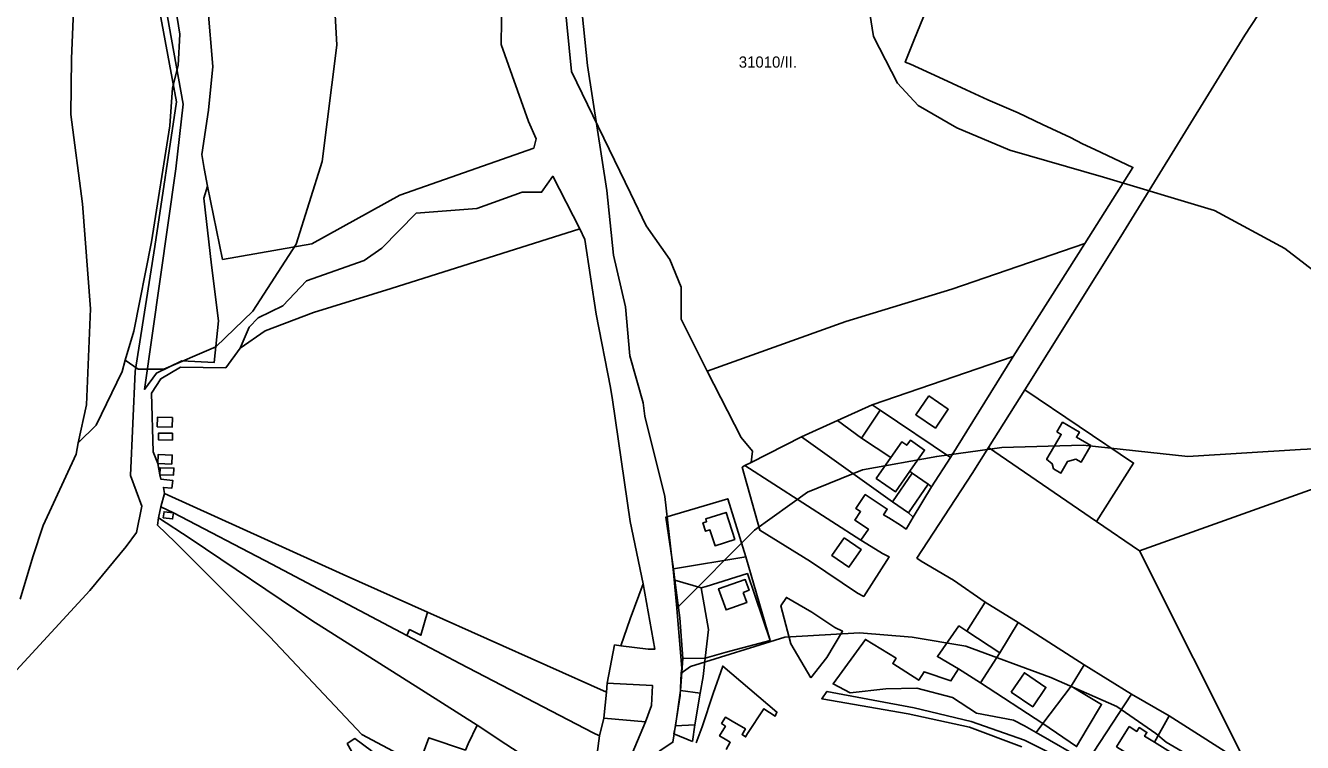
# Model space of a CAD drawing. Extents: x -532083 to -529270, y -1180561 to -1176456.
# Drawn here: x -530779 to -530208, y -1178000 to -1177679 of the extents above; entities that cross this region are included whole.
import ezdxf

# ---------------------------------------------------------------- set-up
doc = ezdxf.new("R2010")
doc.units = 0
for name, color, linetype in [('95560013', 7, 'Continuous'), ('95590013', 7, 'Continuous'), ('95660013', 7, 'Continuous')]:
    doc.layers.add(name, color=color, linetype=linetype)

msp = doc.modelspace()

# ---------------------------------------------------------------- linework, layer by layer
at = {"layer": '95560013'}
for points in [[(-530202.5013, -1177886.43345), (-530280.6013, -1177914.22245), (-530299.8523, -1177901.09045), (-530283.3193, -1177875.02245), (-530332.0333, -1177842.15945), (-530288.9793, -1177773.56145), (-530233.5283, -1177683.50645), (-530208.8843, -1177645.54245), (-530157.0203, -1177563.79845)], [(-530697.4183, -1177670.94245), (-530695.2093, -1177697.53345), (-530697.1583, -1177717.08545), (-530700.1473, -1177736.89845), (-530699.0133, -1177743.09345), (-530697.5383, -1177751.04345), (-530699.1973, -1177756.40545), (-530695.6953, -1177786.35945), (-530692.5613, -1177811.32045), (-530694.5893, -1177829.99545), (-530708.9673, -1177829.25545), (-530720.3953, -1177834.80245), (-530725.7413, -1177842.01345), (-530711.7323, -1177743.27845), (-530708.3573, -1177714.30045), (-530714.6403, -1177679.39445), (-530730.3473, -1177590.91845)], [(-530724.2453, -1177644.04445), (-530711.3873, -1177713.36945), (-530721.0713, -1177777.99645), (-530729.9633, -1177834.02345), (-530731.9083, -1177880.57345), (-530726.9063, -1177894.23145), (-530729.2793, -1177906.09545), (-530733.9793, -1177912.38145), (-530750.1173, -1177932.02645), (-530783.0193, -1177967.70045)], [(-530565.7593, -1177655.31045), (-530566.2513, -1177687.61045), (-530553.9603, -1177722.12945), (-530550.5203, -1177729.84245), (-530551.6063, -1177733.98045), (-530611.5383, -1177755.10845), (-530650.8423, -1177776.89045), (-530690.7973, -1177783.86045), (-530697.5383, -1177751.04345), (-530699.0133, -1177743.09345), (-530700.1473, -1177736.89845), (-530697.1583, -1177717.08545), (-530695.2093, -1177697.53345), (-530697.4183, -1177670.94245)], [(-530377.2153, -1177675.24945), (-530381.6163, -1177685.84645), (-530385.4313, -1177695.55945), (-530383.0843, -1177696.44245), (-530370.4663, -1177702.32945), (-530358.1413, -1177707.92145), (-530348.4583, -1177712.33645), (-530334.9603, -1177718.22345), (-530324.1023, -1177723.52145), (-530311.5343, -1177729.32645), (-530306.2033, -1177732.05745), (-530300.6273, -1177734.70645), (-530283.6203, -1177742.69945), (-530305.1713, -1177776.72145), (-530364.5583, -1177797.10745), (-530412.0683, -1177811.66845), (-530474.0943, -1177833.90845), (-530485.7083, -1177810.60945), (-530485.7083, -1177796.31245), (-530490.7233, -1177783.86945), (-530501.2803, -1177768.77845), (-530508.3383, -1177754.18245), (-530534.7493, -1177699.73945), (-530538.8693, -1177657.20545)], [(-530232.5793, -1178010.35345), (-530280.6013, -1177914.22245), (-530202.5013, -1177886.43345)], [(-530333.2913, -1178002.05245), (-530356.6913, -1177993.25045), (-530384.1853, -1177987.18745), (-530422.7943, -1177980.53745), (-530420.4543, -1177977.21245), (-530381.4553, -1177984.64445), (-530355.9113, -1177990.70845), (-530332.1213, -1177999.11845), (-530297.6073, -1178016.33145)]]:
    msp.add_lwpolyline(points, dxfattribs=at)
for points in [[(-530615.4473, -1177796.92945), (-530650.1913, -1177807.60245), (-530671.6883, -1177815.87945), (-530682.9803, -1177823.50345), (-530678.8543, -1177814.13745), (-530674.9463, -1177809.99845), (-530663.8713, -1177804.55345), (-530653.2313, -1177793.44445), (-530627.3903, -1177784.29645), (-530619.5733, -1177778.85045), (-530604.1553, -1177763.16845), (-530577.0123, -1177760.98945), (-530556.8173, -1177753.80145), (-530548.1313, -1177753.80145), (-530543.1373, -1177746.61345), (-530530.9773, -1177770.13845)], [(-530502.6283, -1177929.02645), (-530508.5273, -1177944.77045), (-530512.6073, -1177956.83045), (-530515.4893, -1177956.38545), (-530518.8153, -1177973.51245), (-530519.0373, -1177977.51645), (-530599.0883, -1177941.70445), (-530636.7923, -1177924.96145), (-530716.7173, -1177888.65345), (-530717.2883, -1177885.88245), (-530713.4193, -1177886.19645), (-530713.0013, -1177882.84045), (-530718.4383, -1177882.21145), (-530718.8563, -1177880.21845), (-530712.6943, -1177880.42345), (-530712.5903, -1177877.27745), (-530718.7523, -1177877.07245), (-530718.8563, -1177880.21845), (-530719.7973, -1177875.18445), (-530713.5243, -1177875.49945), (-530713.3193, -1177871.41345), (-530719.5933, -1177871.09945), (-530719.7973, -1177875.18445), (-530721.8623, -1177870.03945), (-530722.5973, -1177843.68445), (-530718.3713, -1177837.23345), (-530709.5523, -1177832.07345), (-530689.3413, -1177832.44145), (-530682.9803, -1177823.50345), (-530671.6883, -1177815.87945), (-530650.1913, -1177807.60245), (-530615.4473, -1177796.92945), (-530530.9773, -1177770.13845), (-530528.8123, -1177774.98245), (-530523.7273, -1177808.29445), (-530517.2123, -1177841.12945), (-530516.4183, -1177846.70745), (-530508.4383, -1177901.09845)], [(-530400.1913, -1177848.99945), (-530415.7633, -1177855.88245), (-530431.8643, -1177863.29545), (-530454.2993, -1177874.68045), (-530453.7713, -1177869.65045), (-530458.7863, -1177863.56045), (-530474.0943, -1177833.90845), (-530412.0683, -1177811.66845), (-530364.5583, -1177797.10745), (-530305.1713, -1177776.72145), (-530337.1083, -1177827.28945)], [(-530365.1643, -1177872.50345), (-530396.6533, -1177851.28145), (-530400.1913, -1177848.99945), (-530337.1083, -1177827.28945)], [(-530374.9723, -1177844.91245), (-530380.7603, -1177853.37545), (-530371.9853, -1177859.37745), (-530366.1973, -1177850.91445)], [(-530299.8523, -1177901.09045), (-530348.2853, -1177868.05345), (-530332.0333, -1177842.15945), (-530283.3193, -1177875.02245)], [(-530391.9283, -1177872.58045), (-530405.0173, -1177863.86645), (-530396.6533, -1177851.28145), (-530365.1643, -1177872.50345), (-530373.7743, -1177885.58245), (-530375.1473, -1177884.52245), (-530382.3563, -1177879.58145), (-530383.3533, -1177878.58145), (-530376.8033, -1177869.22245), (-530383.1533, -1177864.77845), (-530384.7493, -1177867.05845), (-530386.9743, -1177865.50045)], [(-530720.0073, -1177858.82345), (-530713.3153, -1177858.92845), (-530713.2473, -1177854.63445), (-530719.9393, -1177854.52945)], [(-530317.6183, -1177861.06045), (-530315.7093, -1177862.17445), (-530322.0823, -1177873.09245), (-530322.2123, -1177873.31545), (-530319.6763, -1177875.30045), (-530319.1733, -1177877.52545), (-530315.8523, -1177879.46445), (-530312.8153, -1177874.26245), (-530309.1083, -1177873.29845), (-530306.7753, -1177874.66045), (-530302.4283, -1177867.21445), (-530308.8963, -1177863.43845), (-530307.5593, -1177861.14845), (-530315.1003, -1177856.74745)], [(-530713.1593, -1177861.66145), (-530719.4333, -1177861.55645), (-530719.4843, -1177864.59145), (-530713.2103, -1177864.69645)], [(-530299.8523, -1177901.09045), (-530280.6013, -1177914.22245), (-530232.5793, -1178010.35345), (-530267.4413, -1177988.16645), (-530284.2703, -1177978.51945), (-530305.4283, -1177965.25545), (-530335.0003, -1177946.44445), (-530349.6663, -1177937.28045), (-530363.9053, -1177927.50045), (-530378.2703, -1177918.86645), (-530380.2003, -1177917.50445), (-530355.5573, -1177879.63945), (-530348.2853, -1177868.05345)], [(-530608.4353, -1177952.19945), (-530668.8223, -1177920.26645), (-530712.7923, -1177897.31445), (-530718.4333, -1177894.56345), (-530716.7173, -1177888.65345), (-530636.7923, -1177924.96145), (-530599.0883, -1177941.70445), (-530602.0833, -1177952.09945), (-530607.1643, -1177949.55145)], [(-530456.7093, -1177916.98245), (-530489.1413, -1177922.40445), (-530492.6063, -1177899.23245), (-530464.8373, -1177890.96345)], [(-530712.7923, -1177897.31445), (-530716.9743, -1177896.78945), (-530717.3163, -1177899.51345), (-530713.1333, -1177900.03745), (-530712.7923, -1177897.31445), (-530668.8223, -1177920.26645), (-530608.4353, -1177952.19945), (-530584.7443, -1177964.72645), (-530525.0113, -1177995.73245), (-530522.1413, -1177997.17145), (-530523.1853, -1178005.02045), (-530525.5593, -1178018.51045), (-530526.7383, -1178025.09845), (-530532.6323, -1178021.21245), (-530564.1223, -1178000.77445), (-530576.9413, -1177992.26245), (-530600.2423, -1177977.59245), (-530650.8093, -1177945.51745), (-530705.3423, -1177908.71845), (-530719.4713, -1177899.51845), (-530718.4333, -1177894.56345)], [(-530474.3213, -1177901.24245), (-530475.9523, -1177901.76545), (-530474.7453, -1177905.52645), (-530472.8183, -1177904.90845), (-530470.5333, -1177912.03145), (-530461.6993, -1177909.19745), (-530465.5793, -1177897.10145), (-530474.7103, -1177900.03145)], [(-530456.0163, -1177924.49045), (-530474.4503, -1177930.32945), (-530476.6673, -1177930.88545), (-530488.4483, -1177927.40945), (-530489.1413, -1177922.40445), (-530456.7093, -1177916.98245), (-530445.8983, -1177954.38045)], [(-530445.8983, -1177954.38045), (-530465.5673, -1177959.61645), (-530474.9823, -1177962.40345), (-530473.4803, -1177949.51545), (-530476.6673, -1177930.88545), (-530474.4503, -1177930.32945), (-530456.0163, -1177924.49045)], [(-530500.4103, -1177958.38745), (-530512.6063, -1177956.83045), (-530508.5273, -1177944.77045), (-530502.6283, -1177929.02645), (-530497.5273, -1177958.38745)], [(-530484.8593, -1177962.55745), (-530486.2483, -1177944.29045), (-530488.4483, -1177927.40945), (-530476.6673, -1177930.88545), (-530473.4803, -1177949.51545), (-530474.9823, -1177962.40345)], [(-530457.9603, -1177932.88445), (-530455.2993, -1177931.95345), (-530456.9863, -1177927.13145), (-530468.9063, -1177931.30245), (-530465.6143, -1177940.71045), (-530456.3553, -1177937.47045)], [(-530525.0113, -1177995.73245), (-530584.7443, -1177964.72645), (-530608.4353, -1177952.19945), (-530607.1643, -1177949.55145), (-530602.0833, -1177952.09945), (-530599.0883, -1177941.70445), (-530519.0373, -1177977.51645), (-530520.3153, -1177989.19045), (-530522.1413, -1177997.17145)], [(-530353.5713, -1177986.99145), (-530364.2963, -1177979.95045), (-530380.2853, -1177975.84345), (-530394.1303, -1177976.03845), (-530410.1203, -1177977.79845), (-530417.7243, -1177973.88745), (-530403.2813, -1177953.92045), (-530389.5683, -1177962.41245), (-530391.0643, -1177964.75145), (-530379.4053, -1177972.21145), (-530376.9893, -1177968.43645), (-530365.0533, -1177972.49045), (-530361.6873, -1177967.18445), (-530351.8303, -1177973.45545), (-530323.9403, -1177991.54245), (-530326.8563, -1177995.59845), (-530332.1213, -1177992.66445), (-530336.9963, -1177990.12145)], [(-530486.0203, -1177976.84045), (-530484.8593, -1177962.55745), (-530474.9823, -1177962.40345), (-530475.7773, -1177970.58645), (-530477.1133, -1177977.95745)], [(-530501.6653, -1177990.89145), (-530520.3153, -1177989.19045), (-530519.0373, -1177977.51645), (-530518.8153, -1177973.51245), (-530498.4773, -1177974.59045), (-530498.9263, -1177983.56545)], [(-530479.5623, -1177992.25245), (-530488.2473, -1177992.69945), (-530486.0203, -1177976.84045), (-530477.1133, -1177977.95745)], [(-530507.5343, -1178005.02045), (-530523.1853, -1178005.02045), (-530522.1413, -1177997.17145), (-530520.3153, -1177989.19045), (-530501.6653, -1177990.89145)], [(-530480.6763, -1177999.62345), (-530488.9153, -1177996.27345), (-530488.2473, -1177992.69945), (-530479.5623, -1177992.25245)]]:
    msp.add_lwpolyline(points, close=True, dxfattribs=at)
at = {"layer": '95590013'}
for points in [[(-530405.0173, -1177863.86645), (-530415.7633, -1177855.88245), (-530400.1913, -1177848.99945), (-530396.6533, -1177851.28145)], [(-530391.1313, -1177892.38445), (-530431.8643, -1177863.29545), (-530415.7633, -1177855.88245), (-530405.0173, -1177863.86645), (-530391.9283, -1177872.58045), (-530398.4473, -1177881.89545), (-530389.8723, -1177887.89645), (-530383.3533, -1177878.58145), (-530382.3563, -1177879.58145)], [(-530392.7263, -1177899.58645), (-530395.1533, -1177898.14145), (-530393.4843, -1177895.59645), (-530403.3703, -1177889.11245), (-530407.4843, -1177895.38545), (-530405.4473, -1177896.72145), (-530407.9883, -1177900.59445), (-530401.9003, -1177904.58745), (-530405.2943, -1177909.48145), (-530457.1723, -1177876.16545), (-530454.2993, -1177874.68045), (-530431.8643, -1177863.29545), (-530391.1313, -1177892.38445), (-530383.9223, -1177897.32545), (-530381.8923, -1177899.15445), (-530385.0903, -1177904.58345), (-530387.6443, -1177902.75245)], [(-530427.8963, -1177919.14245), (-530450.5283, -1177905.07245), (-530458.3293, -1177876.89045), (-530457.1723, -1177876.16545), (-530405.2943, -1177909.48145), (-530400.7033, -1177912.38945), (-530395.6213, -1177915.55545), (-530392.7173, -1177916.92145), (-530404.0333, -1177934.68845), (-530406.7393, -1177933.20845)], [(-530381.8923, -1177899.15445), (-530383.9223, -1177897.32545), (-530375.1473, -1177884.52245), (-530373.7743, -1177885.58245)], [(-530602.9683, -1178010.16445), (-530628.5003, -1177996.48945), (-530669.6483, -1177952.72845), (-530712.0353, -1177910.45945), (-530719.9673, -1177902.75145), (-530719.4713, -1177899.51845), (-530705.3423, -1177908.71845), (-530650.8093, -1177945.51745), (-530600.2423, -1177977.59245), (-530576.9413, -1177992.26245), (-530580.9073, -1178000.71645), (-530582.1473, -1178003.45145), (-530598.5073, -1177997.98145)], [(-530412.7913, -1177908.43145), (-530418.2533, -1177916.39045), (-530410.6753, -1177921.59145), (-530405.2133, -1177913.63245)], [(-530427.6603, -1177971.09045), (-530436.5843, -1177955.98445), (-530441.0473, -1177938.92045), (-530438.6323, -1177935.14745), (-530427.1953, -1177941.77645), (-530416.9603, -1177948.58145), (-530413.5103, -1177950.29845), (-530420.5063, -1177962.10045)], [(-530343.1743, -1177959.94945), (-530357.8403, -1177950.30345), (-530349.6663, -1177937.28045), (-530335.0003, -1177946.44445)], [(-530361.6873, -1177967.18445), (-530371.0643, -1177961.63745), (-530361.4473, -1177947.89145), (-530357.8403, -1177950.30345), (-530343.1743, -1177959.94945), (-530351.8303, -1177973.45545)], [(-530323.9403, -1177991.54245), (-530351.8303, -1177973.45545), (-530343.1743, -1177959.94945), (-530335.0003, -1177946.44445), (-530305.4283, -1177965.25545), (-530311.1983, -1177974.90245)], [(-530304.0423, -1178008.70245), (-530326.8563, -1177995.59845), (-530323.9403, -1177991.54245), (-530308.7943, -1178001.91245), (-530304.0193, -1177993.75745), (-530297.6613, -1177983.05845), (-530307.3683, -1177977.28945), (-530311.1983, -1177974.90245), (-530305.4283, -1177965.25545), (-530284.2703, -1177978.51945)], [(-530338.0683, -1177977.50345), (-530328.4283, -1177984.08745), (-530322.5423, -1177975.46945), (-530332.1823, -1177968.88545)], [(-530285.3103, -1177992.98445), (-530290.8923, -1178001.98745), (-530279.6113, -1178008.98245), (-530286.1023, -1178019.26545), (-530304.0423, -1178008.70245), (-530284.2703, -1177978.51945), (-530267.4413, -1177988.16645), (-530274.0223, -1177999.96945), (-530278.3863, -1177997.26345), (-530277.3233, -1177995.55045), (-530280.8163, -1177993.38445), (-530281.8853, -1177995.10845)], [(-530263.1133, -1178020.00045), (-530281.8123, -1178022.00345), (-530286.1023, -1178019.26545), (-530279.6113, -1178008.98245), (-530268.7783, -1178015.70045), (-530263.1893, -1178006.68745), (-530274.0223, -1177999.96945), (-530267.4413, -1177988.16645), (-530232.5793, -1178010.35345)], [(-530597.8053, -1178066.93145), (-530612.5853, -1178040.44245), (-530635.0663, -1178000.54745), (-530631.7043, -1177998.35545), (-530624.2133, -1178003.87245), (-530592.2873, -1178064.95445), (-530595.8353, -1178066.53645)]]:
    msp.add_lwpolyline(points, close=True, dxfattribs=at)
msp.add_lwpolyline([(-530478.8943, -1178000.29345), (-530476.2223, -1177993.14645), (-530471.3233, -1177978.18045), (-530467.0923, -1177965.89545), (-530442.8203, -1177986.44545), (-530443.6013, -1177988.29045), (-530448.6713, -1177984.95945), (-530455.9423, -1177996.02445), (-530456.8593, -1177997.61645), (-530458.3993, -1177996.58545), (-530456.9193, -1177994.00945), (-530462.8693, -1177990.59245), (-530465.9033, -1177988.78945), (-530467.5933, -1177991.56445), (-530465.9033, -1177992.79745), (-530468.5163, -1177997.11345), (-530465.2903, -1177999.08345), (-530463.7443, -1177999.97145), (-530465.5903, -1178003.18545)], dxfattribs=at)
at = {"layer": '95660013'}
for points in [[(-530781.3753, -1177936.00045), (-530775.6253, -1177917.00045), (-530771.0003, -1177903.00045), (-530756.3123, -1177871.00045), (-530755.3123, -1177866.00045), (-530747.3753, -1177858.00045), (-530735.6873, -1177834.00045), (-530734.3753, -1177829.00045), (-530728.5003, -1177833.00045), (-530717.1253, -1177833.00045), (-530693.8123, -1177823.00045), (-530677.1873, -1177807.00045), (-530657.8753, -1177777.00045), (-530646.3123, -1177740.00045), (-530639.6253, -1177688.00045), (-530641.8753, -1177647.00045)], [(-530641.8753, -1177647.00045), (-530639.6253, -1177688.00045), (-530646.3123, -1177740.00045), (-530657.8753, -1177777.00045), (-530677.1873, -1177807.00045), (-530693.8123, -1177823.00045), (-530717.1253, -1177833.00045), (-530728.5003, -1177833.00045), (-530734.3753, -1177829.00045), (-530730.5003, -1177816.00045), (-530722.6253, -1177776.00045), (-530714.3753, -1177724.00045), (-530713.1253, -1177707.00045), (-530710.6253, -1177697.00045), (-530709.8753, -1177683.00045), (-530711.8753, -1177671.00045)], [(-530188.3753, -1177800.00045), (-530215.6253, -1177779.00045), (-530247.1253, -1177762.00045), (-530296.8123, -1177747.00045), (-530338.6253, -1177735.00045), (-530362.3753, -1177725.00045), (-530379.6873, -1177715.00045), (-530388.8753, -1177705.00045), (-530399.6253, -1177684.00045), (-530404.6253, -1177653.00045)], [(-530404.6253, -1177653.00045), (-530399.6253, -1177684.00045), (-530388.8753, -1177705.00045), (-530379.6873, -1177715.00045), (-530362.3753, -1177725.00045), (-530338.6253, -1177735.00045), (-530296.8123, -1177747.00045), (-530247.1253, -1177762.00045), (-530215.6253, -1177779.00045), (-530188.3753, -1177800.00045)], [(-530756.8753, -1177658.00045), (-530758.3123, -1177694.00045), (-530758.6253, -1177719.00045), (-530753.3753, -1177759.00045), (-530749.8123, -1177806.00045), (-530751.6873, -1177849.00045), (-530755.3123, -1177866.00045), (-530756.3123, -1177871.00045), (-530771.0003, -1177903.00045), (-530775.6253, -1177917.00045), (-530781.3753, -1177936.00045)], [(-530711.8753, -1177671.00045), (-530709.8753, -1177683.00045), (-530710.6253, -1177697.00045), (-530713.1253, -1177707.00045), (-530714.3753, -1177724.00045), (-530722.6253, -1177776.00045), (-530730.5003, -1177816.00045), (-530734.3753, -1177829.00045), (-530735.6873, -1177834.00045), (-530747.3753, -1177858.00045), (-530755.3123, -1177866.00045), (-530751.6873, -1177849.00045), (-530749.8123, -1177806.00045), (-530753.3753, -1177759.00045), (-530758.6253, -1177719.00045), (-530758.3123, -1177694.00045), (-530756.8753, -1177658.00045)], [(-530150.3123, -1177866.00045), (-530208.6253, -1177869.00045), (-530259.0003, -1177872.00045), (-530305.8123, -1177867.00045), (-530342.3123, -1177868.00045), (-530371.3753, -1177872.00045), (-530404.6253, -1177878.00045), (-530429.1253, -1177888.00045), (-530452.8753, -1177905.00045), (-530487.6253, -1177940.00045), (-530489.1253, -1177924.00045), (-530493.0003, -1177890.00045), (-530502.0003, -1177854.00045), (-530502.6253, -1177848.00045), (-530508.6253, -1177827.00045), (-530510.6253, -1177805.00045), (-530515.8753, -1177782.00045), (-530518.8753, -1177753.00045), (-530527.5003, -1177697.00045), (-530531.1253, -1177662.00045)], [(-530531.1253, -1177662.00045), (-530527.5003, -1177697.00045), (-530518.8753, -1177753.00045), (-530515.8753, -1177782.00045), (-530510.6253, -1177805.00045), (-530508.6253, -1177827.00045), (-530502.6253, -1177848.00045), (-530502.0003, -1177854.00045), (-530493.0003, -1177890.00045), (-530489.1253, -1177924.00045), (-530487.6253, -1177940.00045), (-530485.3753, -1177967.00045), (-530485.6253, -1177969.00045), (-530486.1253, -1177979.00045), (-530489.3753, -1178000.00045), (-530495.5003, -1178004.00045)], [(-530201.3753, -1178025.00045), (-530221.8123, -1178019.00045), (-530249.8753, -1178011.00045), (-530268.6873, -1178000.00045), (-530273.3753, -1177996.00045), (-530290.8123, -1177984.00045), (-530320.3123, -1177971.00045), (-530358.3753, -1177957.00045), (-530382.3753, -1177953.00045), (-530405.8753, -1177951.00045), (-530439.3123, -1177953.00045), (-530481.5003, -1177966.00045), (-530485.6253, -1177969.00045), (-530485.3753, -1177967.00045), (-530487.6253, -1177940.00045), (-530452.8753, -1177905.00045), (-530429.1253, -1177888.00045), (-530404.6253, -1177878.00045), (-530371.3753, -1177872.00045), (-530342.3123, -1177868.00045), (-530305.8123, -1177867.00045), (-530259.0003, -1177872.00045), (-530208.6253, -1177869.00045), (-530150.3123, -1177866.00045)], [(-530495.5003, -1178004.00045), (-530489.3753, -1178000.00045), (-530486.1253, -1177979.00045), (-530485.6253, -1177969.00045), (-530481.5003, -1177966.00045), (-530439.3123, -1177953.00045), (-530405.8753, -1177951.00045), (-530382.3753, -1177953.00045), (-530358.3753, -1177957.00045), (-530320.3123, -1177971.00045), (-530290.8123, -1177984.00045), (-530273.3753, -1177996.00045), (-530268.6873, -1178000.00045), (-530249.8753, -1178011.00045)]]:
    msp.add_lwpolyline(points, dxfattribs=at)

# ---------------------------------------------------------------- texts
msp.add_text('31010/II.', height=5, dxfattribs=at).set_placement((-530459.90246, -1177698.00045))

doc.saveas('drawing.dxf')
